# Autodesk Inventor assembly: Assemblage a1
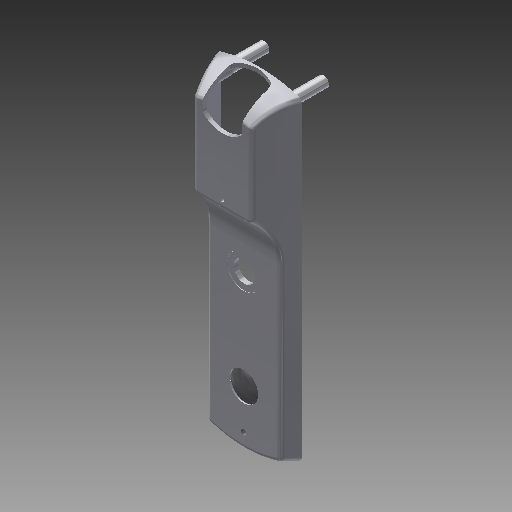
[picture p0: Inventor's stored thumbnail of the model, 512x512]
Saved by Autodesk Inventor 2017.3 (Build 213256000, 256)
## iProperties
Created: 2007-12
Part Number: Assemblage a1
Material: Générique
Document SubType Name: Assembly
Designer: ficho
Author: ficho
Sending System: SolidWorks 2009
Last Author: christophe
Last Saved: 2011-02-10
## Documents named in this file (8)
- G:\travail\année 2019-2020\réforme\toussaint\Serrure biométrique SET\Documentations_pedagogique\Modelisation_Solidworks\Assemblage a1.iam
- G:\travail\année 2019-2020\réforme\toussaint\Serrure biométrique SET\Documentations_pedagogique\Modelisation_Solidworks\piece a1.ipt
- G:\travail\année 2019-2020\réforme\toussaint\Serrure biométrique SET\Documentations_pedagogique\Modelisation_Solidworks\pièce a9.ipt
- G:\travail\année 2019-2020\réforme\toussaint\Serrure biométrique SET\Documentations_pedagogique\Modelisation_Solidworks\pièce a8.ipt
- G:\travail\année 2019-2020\réforme\toussaint\Serrure biométrique SET\Documentations_pedagogique\Modelisation_Solidworks\pièce a27.ipt
- G:\travail\année 2019-2020\réforme\toussaint\Serrure biométrique SET\Documentations_pedagogique\Modelisation_Solidworks\pièce a26.ipt
- G:\travail\année 2019-2020\réforme\toussaint\Serrure biométrique SET\Documentations_pedagogique\Modelisation_Solidworks\piece a20.ipt
- G:\travail\année 2019-2020\réforme\toussaint\Serrure biométrique SET\Documentations_pedagogique\Modelisation_Solidworks\piece a21.ipt
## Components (13 placed, 7 different names)
1. piece a1:1
2. pièce a9:4
3. pièce a9:5
4. pièce a9:6
5. pièce a8:1
6. pièce a8:2
7. pièce a27:1
8. pièce a8:3
9. pièce a26:1
10. piece a20:1
11. piece a20:2
12. piece a21:1
13. piece a21:2
